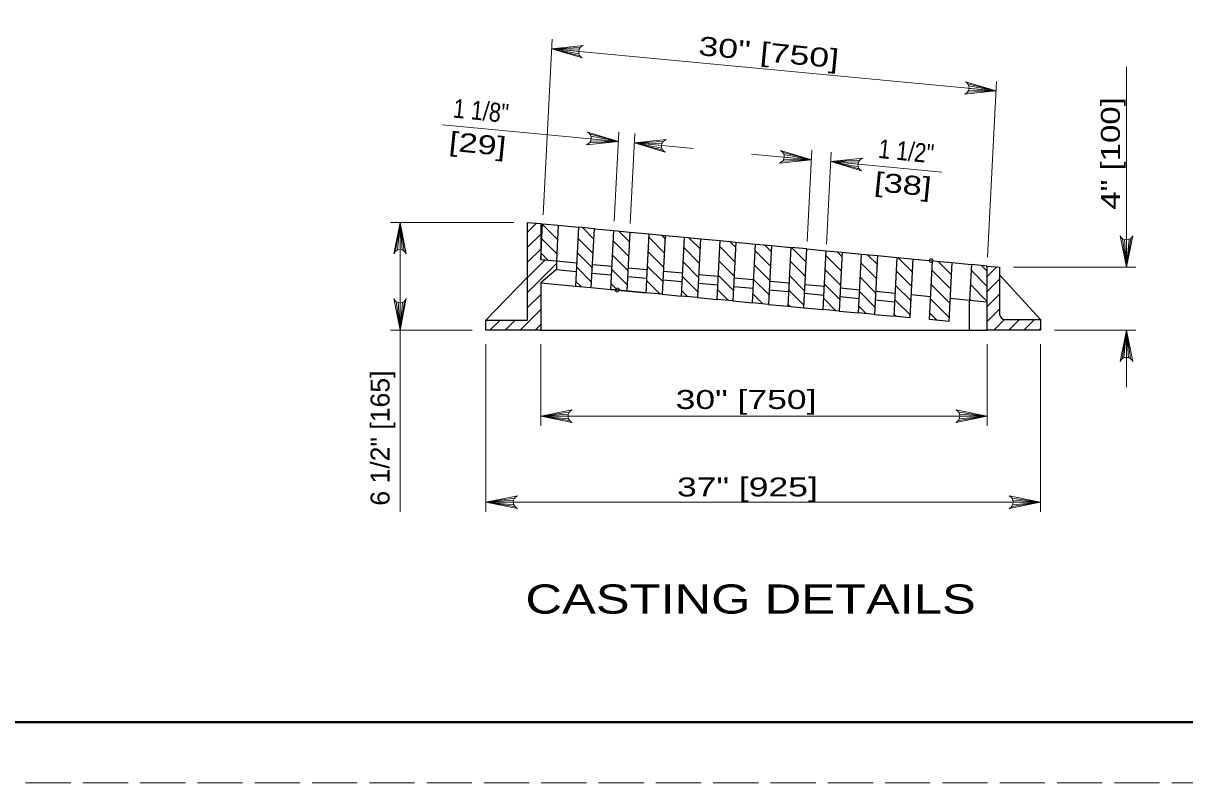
# Model space of a CAD drawing. Extents: x 1083.1 to 1123, y 697.4 to 741.4.
# Drawn here: x 1101.99 to 1111.55, y 697.35 to 703.61 of the extents above; entities that cross this region are included whole.
import ezdxf
from ezdxf.enums import TextEntityAlignment as Align

# ---------------------------------------------------------------- set-up
doc = ezdxf.new("R2010")
doc.units = 0
doc.header["$LTSCALE"] = 0.062
doc.header["$PDMODE"] = 32
doc.header["$PDSIZE"] = 0.031
doc.linetypes.add('LONG_DASHED', pattern=[7.5, 6, -1.5])
doc.layers.add('1', color=7, linetype='Continuous', lineweight=13)

msp = doc.modelspace()

# ---------------------------------------------------------------- linework, layer by layer
at = {"layer": '1'}
for p, q in [((1106.26917, 702.03067), (1106.34333, 703.4765)), ((1106.57592, 703.40833), (1106.33925, 703.39783)), ((1106.5625, 703.37667), (1106.33925, 703.39783)), ((1106.56467, 703.35525), (1106.33925, 703.39783)), ((1106.57217, 703.33925), (1106.33925, 703.39783)), ((1106.5665, 703.39292), (1106.33925, 703.39783)), ((1106.33925, 703.39783), (1110.00083, 703.04983)), ((1111.07392, 703.24733), (1111.07392, 701.59875)), ((1109.76792, 703.10842), (1110.00083, 703.04983)), ((1109.77542, 703.09242), (1110.00083, 703.04983)), ((1109.93058, 701.68192), (1110.00483, 703.12842)), ((1109.76417, 703.03933), (1110.00083, 703.04983)), ((1109.77358, 703.05475), (1110.00083, 703.04983)), ((1109.77758, 703.07108), (1110.00083, 703.04983)), ((1105.441, 702.772), (1106.88925, 702.63433)), ((1106.85558, 701.97667), (1106.89325, 702.713)), ((1106.6525, 702.62392), (1106.88925, 702.63433)), ((1106.65633, 702.69292), (1106.88925, 702.63433)), ((1106.662, 702.63933), (1106.88925, 702.63433)), ((1106.66383, 702.677), (1106.88925, 702.63433)), ((1106.666, 702.65558), (1106.88925, 702.63433)), ((1106.98658, 701.958), (1107.02467, 702.7005)), ((1107.25733, 702.63233), (1107.02067, 702.62192)), ((1107.24392, 702.60067), (1107.02067, 702.62192)), ((1107.246, 702.57933), (1107.02067, 702.62192)), ((1107.2535, 702.56333), (1107.02067, 702.62192)), ((1107.24783, 702.61692), (1107.02067, 702.62192)), ((1107.02067, 702.62192), (1107.50692, 702.57567)), ((1107.9855, 702.53017), (1108.47858, 702.48333)), ((1108.24567, 702.54192), (1108.47858, 702.48333)), ((1108.25317, 702.52592), (1108.47858, 702.48333)), ((1108.444, 701.81058), (1108.48258, 702.56192)), ((1108.604, 701.78875), (1108.64283, 702.54675)), ((1108.24192, 702.47283), (1108.47858, 702.48333)), ((1108.25133, 702.48825), (1108.47858, 702.48333)), ((1108.25533, 702.5045), (1108.47858, 702.48333)), ((1108.8755, 702.47858), (1108.63883, 702.46808)), ((1108.86208, 702.44683), (1108.63883, 702.46808)), ((1108.86417, 702.4255), (1108.63883, 702.46808)), ((1108.87167, 702.4095), (1108.63883, 702.46808)), ((1108.866, 702.46317), (1108.63883, 702.46808)), ((1108.63883, 702.46808), (1109.55308, 702.38117)), ((1106.02708, 701.96733), (1105.01208, 701.96733)), ((1105.0545, 701.73), (1105.09075, 701.96733)), ((1105.06967, 701.739), (1105.09075, 701.96733)), ((1105.09075, 701.74308), (1105.09075, 701.96733)), ((1105.10733, 701.74067), (1105.09075, 701.96733)), ((1105.12358, 701.73275), (1105.09075, 701.96733)), ((1105.09075, 699.58383), (1105.09075, 701.96733)), ((1106.14142, 701.887), (1106.21483, 701.96042)), ((1106.25025, 701.95717), (1106.26525, 701.95567)), ((1106.38817, 701.82675), (1106.265, 701.94992)), ((1106.14142, 701.76283), (1106.25025, 701.87167)), ((1106.68692, 701.83083), (1106.59317, 701.92458)), ((1106.97892, 701.809), (1106.89158, 701.89625)), ((1107.27317, 701.83458), (1107.24483, 701.86283)), ((1106.14142, 701.63875), (1106.25025, 701.7475)), ((1106.38208, 701.70858), (1106.25892, 701.83192)), ((1106.68092, 701.71275), (1106.5555, 701.83808)), ((1106.97275, 701.69083), (1106.84742, 701.81625)), ((1107.26717, 701.7165), (1107.14167, 701.84192)), ((1107.55575, 701.63167), (1107.43033, 701.757)), ((1107.56183, 701.74983), (1107.47008, 701.8415)), ((1107.84933, 701.64275), (1107.72392, 701.76825)), ((1107.8555, 701.76092), (1107.80683, 701.80958)), ((1108.14667, 701.72725), (1108.09142, 701.7825)), ((1108.43525, 701.64083), (1108.31475, 701.76133)), ((1111.04108, 701.83333), (1111.07392, 701.59875)), ((1111.05733, 701.82542), (1111.07392, 701.59875)), ((1111.11025, 701.83617), (1111.07392, 701.59875)), ((1111.095, 701.82717), (1111.07392, 701.59875)), ((1111.07392, 701.823), (1111.07392, 701.59875)), ((1106.14142, 701.5145), (1106.28617, 701.65925)), ((1106.3095, 701.657), (1106.25275, 701.71375)), ((1106.67483, 701.59458), (1106.5495, 701.72)), ((1106.96667, 701.57275), (1106.84133, 701.69817)), ((1107.26108, 701.59842), (1107.13558, 701.72383)), ((1108.14058, 701.60908), (1108.01525, 701.73458)), ((1108.7245, 701.5685), (1108.59917, 701.69383)), ((1108.73058, 701.68667), (1108.69167, 701.72558)), ((1109.02033, 701.62375), (1108.94242, 701.70167)), ((1109.31008, 701.55975), (1109.19167, 701.67817)), ((1109.32892, 701.66508), (1109.32892, 701.66517)), ((1106.14142, 701.39033), (1106.37917, 701.628)), ((1106.66875, 701.47658), (1106.54342, 701.60192)), ((1106.96075, 701.45475), (1106.83525, 701.58008)), ((1107.255, 701.48033), (1107.12958, 701.60567)), ((1107.54975, 701.51367), (1107.42425, 701.639)), ((1107.84325, 701.52475), (1107.71792, 701.65008)), ((1108.1345, 701.49108), (1108.00917, 701.61642)), ((1108.42925, 701.52267), (1108.30375, 701.64817)), ((1108.7185, 701.4505), (1108.593, 701.57583)), ((1109.01433, 701.50558), (1108.88892, 701.63108)), ((1109.304, 701.44167), (1109.17867, 701.56708)), ((1109.62525, 701.42058), (1109.47192, 701.57383)), ((1109.63133, 701.53867), (1109.52325, 701.64667)), ((1109.92683, 701.44108), (1109.79425, 701.57367)), ((1109.92683, 701.56533), (1109.87917, 701.613)), ((1109.92683, 701.52267), (1110.00508, 701.60108)), ((1110.14375, 701.59875), (1111.15258, 701.59875)), ((1106.58192, 701.43925), (1106.53733, 701.48392)), ((1106.88025, 701.411), (1106.82917, 701.46192)), ((1107.23367, 701.37742), (1107.1235, 701.48767)), ((1107.54367, 701.3955), (1107.41825, 701.52092)), ((1107.83717, 701.40667), (1107.71183, 701.53208)), ((1108.1285, 701.37292), (1108.003, 701.49842)), ((1108.42317, 701.40458), (1108.29767, 701.53)), ((1109.00825, 701.38758), (1108.88275, 701.51292)), ((1109.92683, 701.3985), (1110.02933, 701.50108)), ((1106.14142, 701.26625), (1106.25025, 701.375)), ((1106.66642, 701.43117), (1106.66642, 701.43108)), ((1106.88025, 701.41083), (1106.88025, 701.411)), ((1107.11842, 701.38842), (1107.11842, 701.38825)), ((1107.45892, 701.35608), (1107.41217, 701.40283)), ((1107.79558, 701.32417), (1107.70575, 701.41392)), ((1108.08008, 701.29708), (1107.99708, 701.38025)), ((1108.41708, 701.28658), (1108.29167, 701.41192)), ((1108.71242, 701.33233), (1108.58708, 701.45775)), ((1109.00217, 701.26942), (1108.87683, 701.39483)), ((1109.298, 701.3235), (1109.17258, 701.449)), ((1109.61908, 701.30242), (1109.46592, 701.45575)), ((1109.92683, 701.31692), (1109.78825, 701.45558)), ((1109.92683, 701.27442), (1110.02933, 701.37692)), ((1105.05792, 701.31517), (1105.09075, 701.0805)), ((1105.07417, 701.30717), (1105.09075, 701.0805)), ((1105.12708, 701.31792), (1105.09075, 701.0805)), ((1105.11183, 701.30892), (1105.09075, 701.0805)), ((1105.09075, 701.30475), (1105.09075, 701.0805)), ((1107.41, 701.36075), (1107.41, 701.36058)), ((1108.3035, 701.27583), (1108.28558, 701.29375)), ((1108.6805, 701.24017), (1108.581, 701.33967)), ((1108.93092, 701.2165), (1108.87075, 701.27667)), ((1109.29192, 701.2055), (1109.16642, 701.33083)), ((1109.61317, 701.18442), (1109.45983, 701.33767)), ((1109.79292, 701.32667), (1109.78217, 701.33742)), ((1106.07983, 701.0805), (1106.25025, 701.25083)), ((1109.1805, 701.19283), (1109.1605, 701.21283)), ((1109.51192, 701.16133), (1109.45375, 701.2195)), ((1109.92683, 701.15025), (1110.02933, 701.25283)), ((1105.68442, 701.0805), (1105.01208, 701.0805)), ((1105.83158, 701.0805), (1105.91417, 701.16308)), ((1105.95575, 701.0805), (1106.03825, 701.16308)), ((1106.20417, 701.0805), (1106.25025, 701.12658)), ((1109.98117, 701.0805), (1110.06975, 701.16892)), ((1110.1055, 701.0805), (1110.19325, 701.16833)), ((1110.22958, 701.0805), (1110.31742, 701.16833)), ((1110.35375, 701.0805), (1110.36592, 701.09267)), ((1110.48033, 701.0805), (1111.15258, 701.0805)), ((1110.72092, 701.08067), (1110.72092, 701.0805)), ((1111.03767, 700.84317), (1111.07392, 701.0805)), ((1111.05283, 700.85208), (1111.07392, 701.0805)), ((1111.07392, 700.85625), (1111.07392, 701.0805)), ((1111.0905, 700.85383), (1111.07392, 701.0805)), ((1111.10675, 700.84592), (1111.07392, 701.0805)), ((1111.07392, 701.0805), (1111.07392, 700.6105)), ((1105.79875, 700.96617), (1105.79875, 699.58583)), ((1106.25025, 700.96617), (1106.25025, 700.29383)), ((1109.92683, 700.96617), (1109.92683, 700.29383)), ((1110.36592, 700.96617), (1110.36592, 699.58583)), ((1106.48483, 700.40533), (1106.25025, 700.3725)), ((1106.47692, 700.38908), (1106.25025, 700.3725)), ((1106.4745, 700.3725), (1106.25025, 700.3725)), ((1106.47867, 700.35142), (1106.25025, 700.3725)), ((1106.48758, 700.33625), (1106.25025, 700.3725)), ((1106.25025, 700.3725), (1109.92683, 700.3725)), ((1109.68942, 700.33625), (1109.92683, 700.3725)), ((1109.69217, 700.40533), (1109.92683, 700.3725)), ((1109.69842, 700.35142), (1109.92683, 700.3725)), ((1109.70017, 700.38908), (1109.92683, 700.3725)), ((1109.70258, 700.3725), (1109.92683, 700.3725)), ((1106.03342, 699.69733), (1105.79875, 699.6645)), ((1106.02542, 699.68108), (1105.79875, 699.6645)), ((1106.023, 699.6645), (1105.79875, 699.6645)), ((1106.02717, 699.64342), (1105.79875, 699.6645)), ((1106.03617, 699.62825), (1105.79875, 699.6645)), ((1105.79875, 699.6645), (1110.36592, 699.6645)), ((1110.12858, 699.62825), (1110.36592, 699.6645)), ((1110.13133, 699.69733), (1110.36592, 699.6645)), ((1110.13758, 699.64342), (1110.36592, 699.6645)), ((1110.13925, 699.68108), (1110.36592, 699.6645)), ((1110.14167, 699.6645), (1110.36592, 699.6645))]:
    msp.add_line(p, q, dxfattribs=at)
at = {"layer": '1', "lineweight": 25}
for p, q in [((1106.14142, 701.96733), (1106.25025, 701.95717)), ((1106.25025, 701.66267), (1106.26525, 701.95567)), ((1106.26525, 701.95567), (1106.39417, 701.9435)), ((1106.39417, 701.9435), (1106.37917, 701.65042)), ((1106.39417, 701.9435), (1106.56008, 701.92775)), ((1106.56008, 701.92758), (1106.53525, 701.4435)), ((1106.69133, 701.91533), (1106.56008, 701.92775)), ((1106.66642, 701.43108), (1106.69133, 701.91517)), ((1106.69133, 701.91533), (1106.85167, 701.90008)), ((1106.98292, 701.88758), (1107.14325, 701.8725)), ((1107.11842, 701.38825), (1107.14325, 701.87242)), ((1107.14325, 701.8725), (1107.2745, 701.86008)), ((1107.2745, 701.85992), (1107.24958, 701.37583)), ((1107.2745, 701.86008), (1107.43483, 701.84483)), ((1107.41, 701.36058), (1107.43483, 701.84467)), ((1107.43483, 701.84483), (1107.56608, 701.83242)), ((1107.56608, 701.83225), (1107.54117, 701.34817)), ((1107.56608, 701.83242), (1107.72642, 701.81717)), ((1107.85767, 701.80467), (1108.018, 701.7895)), ((1108.14925, 701.777), (1108.30958, 701.76175)), ((1108.44083, 701.74933), (1108.60117, 701.73408)), ((1108.73242, 701.72167), (1108.89275, 701.70642)), ((1108.89275, 701.70642), (1109.024, 701.694)), ((1109.024, 701.694), (1109.18433, 701.67883)), ((1106.37917, 701.65042), (1106.545, 701.63475)), ((1106.37917, 701.57842), (1106.54133, 701.563)), ((1106.67633, 701.62225), (1106.83667, 701.60717)), ((1106.96792, 701.59475), (1107.12825, 701.57958)), ((1107.2595, 701.56708), (1107.41983, 701.55192)), ((1109.63633, 701.63608), (1109.79667, 701.62083)), ((1109.92683, 701.0805), (1109.92683, 701.6085)), ((1105.79875, 701.16308), (1106.14142, 701.51667)), ((1106.25025, 701.47058), (1106.53525, 701.44367)), ((1106.67258, 701.55058), (1106.83292, 701.53542)), ((1106.96417, 701.52292), (1107.1245, 701.50767)), ((1107.25575, 701.49533), (1107.41608, 701.48008)), ((1107.54733, 701.46767), (1107.70767, 701.45242)), ((1107.55108, 701.5395), (1107.71142, 701.52433)), ((1107.8425, 701.51183), (1108.003, 701.49658)), ((1108.13425, 701.48417), (1108.29458, 701.46892)), ((1110.36592, 701.16833), (1110.02933, 701.53542)), ((1106.53525, 701.44367), (1106.66642, 701.43117)), ((1106.66642, 701.43117), (1106.82683, 701.416)), ((1107.24958, 701.376), (1107.11842, 701.38842)), ((1107.24958, 701.376), (1107.41, 701.36075)), ((1107.83892, 701.44), (1107.99925, 701.42483)), ((1108.1305, 701.41242), (1108.29083, 701.39733)), ((1108.42208, 701.38475), (1108.58242, 701.3695)), ((1108.42583, 701.45642), (1108.58617, 701.44117)), ((1108.71742, 701.42875), (1108.87775, 701.4135)), ((1109.00892, 701.40108), (1109.16933, 701.38583)), ((1109.30058, 701.37342), (1109.46092, 701.35817)), ((1107.54117, 701.34825), (1107.41, 701.36075)), ((1107.83275, 701.32058), (1107.99317, 701.30533)), ((1108.12433, 701.29292), (1108.28475, 701.27767)), ((1108.71367, 701.35708), (1108.874, 701.34183)), ((1109.00525, 701.3295), (1109.16558, 701.31425)), ((1109.62133, 701.34308), (1109.78167, 701.32783)), ((1109.78167, 701.0805), (1109.78167, 701.32783)), ((1108.41592, 701.26525), (1108.57633, 701.25)), ((1108.70758, 701.23758), (1108.57633, 701.25)), ((1108.99917, 701.21), (1109.1595, 701.19475)), ((1106.25025, 701.0805), (1109.92683, 701.0805))]:
    msp.add_line(p, q, dxfattribs=at)
at = {"layer": '1', "linetype": 'LONG_DASHED'}
msp.add_lwpolyline([(1083.12642, 697.35408), (1117.12642, 697.35408), (1117.12642, 719.35408), (1083.12642, 719.35408)], close=True, dxfattribs=at)
at = {"layer": '1', "lineweight": 25}
for points in [[(1116.62642, 697.85408), (1085.12642, 697.85408), (1085.12642, 718.85408)], [(1106.37917, 701.57842), (1106.25025, 701.47058), (1106.25025, 701.0805), (1105.79875, 701.0805), (1105.79875, 701.16308), (1106.14142, 701.16308), (1106.14142, 701.96733)], [(1106.25025, 701.957), (1106.25025, 701.66267), (1106.37917, 701.65042), (1106.37917, 701.57608)], [(1106.82683, 701.416), (1106.85167, 701.90008), (1106.98292, 701.88758), (1106.958, 701.4035)], [(1107.54117, 701.34825), (1107.70158, 701.33308), (1107.72642, 701.81717), (1107.85767, 701.80467), (1107.83275, 701.32058), (1107.70158, 701.33308)], [(1108.57633, 701.25), (1108.60117, 701.73408), (1108.73242, 701.72167), (1108.70758, 701.23767)], [(1108.70758, 701.23758), (1108.86792, 701.22242), (1108.89275, 701.7065)], [(1109.024, 701.69408), (1108.99917, 701.21), (1108.86792, 701.22242)], [(1109.1595, 701.19475), (1109.18433, 701.67883), (1109.47592, 701.65117)], [(1109.31558, 701.66642), (1109.29075, 701.18233), (1109.1595, 701.19475)], [(1109.92683, 701.6085), (1109.79667, 701.62083), (1109.78167, 701.32783), (1109.92683, 701.314)], [(1109.92683, 701.6085), (1110.02933, 701.59875), (1110.02933, 701.21217)], [(1106.82683, 701.416), (1107.11842, 701.38842), (1106.82683, 701.416)], [(1110.07325, 701.16833), (1110.36592, 701.16833), (1110.36592, 701.0805), (1109.92683, 701.0805)]]:
    msp.add_lwpolyline(points, dxfattribs=at)
at = {"layer": '1', "lineweight": 40}
msp.add_lwpolyline([(1085.12642, 718.85408), (1116.62642, 718.85408), (1116.62642, 697.85408), (1085.12642, 697.85408)], close=True, dxfattribs=at)
at = {"layer": '1'}
for points in [[(1106.59233, 703.32175), (1106.33925, 703.39783), (1106.60217, 703.42492)], [(1109.74775, 703.12592), (1110.00083, 703.04983), (1109.73792, 703.02275)], [(1106.63617, 702.7105), (1106.88925, 702.63433), (1106.62633, 702.60733)], [(1107.27375, 702.54575), (1107.02067, 702.62192), (1107.2835, 702.649)], [(1108.2255, 702.55942), (1108.47858, 702.48333), (1108.21567, 702.45625)], [(1108.89192, 702.392), (1108.63883, 702.46808), (1108.90167, 702.49517)], [(1105.03892, 701.70825), (1105.09075, 701.96733), (1105.14258, 701.70825)], [(1111.12575, 701.85792), (1111.07392, 701.59875), (1111.02208, 701.85792)], [(1105.14258, 701.33967), (1105.09075, 701.0805), (1105.03892, 701.33967)], [(1111.02208, 700.82133), (1111.07392, 701.0805), (1111.12575, 700.82133)], [(1106.50933, 700.32067), (1106.25025, 700.3725), (1106.50933, 700.42433)], [(1109.66767, 700.32067), (1109.92683, 700.3725), (1109.66767, 700.42433)], [(1106.05792, 699.61267), (1105.79875, 699.6645), (1106.05792, 699.71633)], [(1110.10683, 699.61267), (1110.36592, 699.6645), (1110.10683, 699.71633)]]:
    msp.add_lwpolyline(points, dxfattribs=at)
at = {"layer": '1', "lineweight": 25}
for points in [[(1107.99317, 701.30533), (1108.018, 701.7895), (1108.14925, 701.777), (1108.12433, 701.29292)], [(1108.41592, 701.26525), (1108.44083, 701.74933), (1108.30958, 701.76175), (1108.28475, 701.27767)], [(1109.45108, 701.16708), (1109.47592, 701.65117), (1109.63633, 701.63608), (1109.61142, 701.152)]]:
    msp.add_lwpolyline(points, close=True, dxfattribs=at)
at = {"layer": '1'}
for centre, start, end in [((1106.61809, 703.3714), 106.65835, 242.48447), ((1109.72199, 703.07627), 286.65835, 62.48447), ((1106.61039, 702.66082), 286.65835, 62.48447), ((1107.29947, 702.59544), 106.65835, 242.48447), ((1108.19973, 702.50976), 286.65835, 62.48447), ((1108.91763, 702.44165), 106.65835, 242.48447), ((1111.07389, 701.87883), 202.08782, 337.91395), ((1105.09082, 701.68729), 22.08782, 157.91395), ((1105.09071, 701.36059), 202.08782, 337.91395), ((1111.074, 700.80043), 22.08782, 157.91395), ((1106.5303, 700.37257), 112.08782, 247.91395), ((1109.64673, 700.37257), 292.08605, 67.91218), ((1106.07884, 699.66456), 112.08782, 247.91395), ((1110.08588, 699.66456), 292.08605, 67.91218)]:
    msp.add_arc(centre, 0.05593, start, end, dxfattribs=at)
at = {"layer": '1', "lineweight": 25}
msp.add_ellipse((1110.07327, 701.21221), major_axis=(-0.0439, 0), ratio=0.999895, start_param=6.2831853, end_param=7.8539816, dxfattribs=at)
at = {"layer": '1'}
for p in [(1109.46608, 701.65217), (1106.88025, 701.411)]:
    msp.add_point(p, dxfattribs=at)

# ---------------------------------------------------------------- texts
for s, rotation, width, p in [('30" [750]', 354.57, 1.4, (1107.54375, 703.34517)), ('4" [100]', 90, 1.3, (1111.02008, 702.07242)), ('6 1/2" [165]', 90, 1.05, (1105.00433, 699.63517))]:
    msp.add_text(s, height=0.156, rotation=rotation, dxfattribs=dict(at, width=width)).set_placement(p)
for s, width, p in [('1 1/8"', 0.85, (1105.74981, 702.80879)), ('[29]', 1.35, (1105.72256, 702.53619)), ('1 1/2"', 0.85, (1109.25248, 702.47621)), ('[38]', 1.35, (1109.22527, 702.20358))]:
    msp.add_text(s, height=0.156, rotation=354.311, dxfattribs=dict(at, width=width)).set_placement(p, align=Align.CENTER)
at = {"layer": '1', "width": 1.4}
for s, p in [('30" [750]', (1107.36125, 700.43142)), ('37" [925]', (1107.37225, 699.71142))]:
    msp.add_text(s, height=0.156, dxfattribs=at).set_placement(p)
at = {"layer": '1', "width": 1.3}
msp.add_text('CASTING DETAILS', height=0.24, dxfattribs=at).set_placement((1107.97842, 698.74667), align=Align.CENTER)

doc.saveas('drawing.dxf')
